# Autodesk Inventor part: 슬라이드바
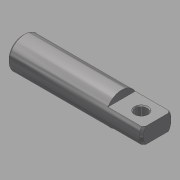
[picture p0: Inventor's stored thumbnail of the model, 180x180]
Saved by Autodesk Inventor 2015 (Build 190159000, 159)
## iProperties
Created: 2015-12
Part Number: 슬라이드바
Material: 스테인리스강
Document SubType Name: Modeling
Designer: mduedu
Density: 8.08 g/cm^3
Appearance: 반광택
Author: mduedu
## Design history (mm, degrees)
sketch "스케치1"
  geometry: L1 (-34, 0)-(34, 0); L2 (-34, 0)-(-34, 8); L3 (-34, 8)-(34, 8); L4 (34, 8)-(34, 0); 2 further points
  constraints: 8 end point, 2 perpendicular, 1 coincident, 1 horizontal, 1 midpoint, 1 vertical
  dimensions: "d0" = 68 distance of L2.end L3.end; "d2" = 16 diameter of L3 L1
revolve "회전1" sketch "스케치1" stored, may be unused: angle "d3" = 90 deg
sketch "스케치2"
  geometry: L1 (34, -8)-(34, 8) reference; L2 (0, 0)-(34, 0); L3 (34, 4)-(16, 4); L4 (16, 4)-(16, 8); L5 (16, 8)-(34, 8); L6 (34, 8)-(34, 4); L7 (-34, 8)-(34, 8) reference
  constraints: 10 end point, 2 parallel, 1 collinear, 1 horizontal, 1 midpoint, 1 perpendicular, 1 point on line
  dimensions: "d4" = 18 distance of L4.end L5.end; "d6" = 4 distance between parallel lines of L3 L2
extrude "돌출1" cut sketch "스케치2" stored distance "d8" = 10; taper "d9" = 0 deg
sketch "스케치3"
  geometry: L1 (0, 0)-(0, -13.856) reference; 2 further points
  constraints: 1 horizontal alignment
  dimensions: "d10" = 10 distance from line of point (10, -6.928) L1
hole "구멍1" sketch "스케치3" at (10, -6.928) diameter "d11" = 6; stored, may be unused: countersink angle "d15" = 90 deg, drill point angle "d17" = 118 deg; dims "d12" = 6, "d13" = 4, "d14" = 2, "d16" = 8
chamfer "모따기1" distance "d18" = 0.5; stored, may be unused: second distance "d19" = 2, angle "d20" = 45 deg
chamfer "모따기2" distance "d21" = 1; stored, may be unused: second distance "d22" = 2, angle "d23" = 45 deg
hole "구멍2" diameter "d26" = 4.917; stored, may be unused: countersink angle "d30" = 90 deg, drill point angle "d32" = 118 deg; dims "d24" = 10, "d25" = 10, "d27" = 12, "d28" = 4, "d29" = 2, "d31" = 13
chamfer "모따기3" distance "d33" = 1; stored, may be unused: second distance "d34" = 2, angle "d35" = 45 deg
node "솔리드1"
mirror "대칭1"
